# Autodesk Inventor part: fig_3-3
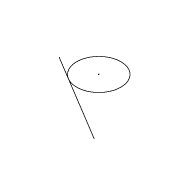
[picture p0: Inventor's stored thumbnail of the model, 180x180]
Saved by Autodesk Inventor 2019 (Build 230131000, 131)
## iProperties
Created: 2009-11
Part Number: fig_3-3
Document SubType Name: Modeling
Designer: Sham
Density: 1 g/cm^3
Material: Generic
Appearance: Default
Author: Sham
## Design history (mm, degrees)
sketch "Sketch1"
  geometry: L1 (-21, -10.296)-(20, -35); C1 r 10.296 at (-4.831, -8.018)
  constraints: 2 end point, 1 centre point, 1 tangent, 1 other
